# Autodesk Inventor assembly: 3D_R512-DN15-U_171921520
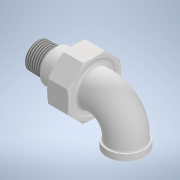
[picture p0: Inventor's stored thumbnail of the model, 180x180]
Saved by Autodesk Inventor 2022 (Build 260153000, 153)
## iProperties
Created: 2021-07
Part Number: 3D_R512-DN15-U_171921520
Document SubType Name: Assembly
Designer: cad
Author: cad
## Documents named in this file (4)
- C:\Users\cad\Desktop\Winkelverschraubung\R-512-U\3D_R512-DN15-U_171921520.iam
- C:\Users\cad\Desktop\Winkelverschraubung\Einzelteile\Mutter\Mutter-DN15.ipt
- C:\Users\cad\Desktop\Winkelverschraubung\Einzelteile\Einschraubteil-R512\Einschraubteil-R512-DN15.ipt
- C:\Users\cad\Desktop\Winkelverschraubung\Einzelteile\Einlegeteil-R512-U\Einlegeteil-R512-U-DN15.ipt
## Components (3 placed, 3 different names)
1. Mutter-DN15:1 — Passend:1, Passend:2, Passend:3, Passend:5
2. Einschraubteil-R512-DN15:1 — Passend:4, Passend:5
3. Einlegeteil-R512-U-DN15:1 — Passend:1, Passend:2, Passend:3, Passend:4
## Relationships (5: Mate 5)
- Passend:1 [Mate]: Mutter-DN15:1 ↔ Einlegeteil-R512-U-DN15:1
- Passend:2 [Mate]: Mutter-DN15:1 ↔ Einlegeteil-R512-U-DN15:1
- Passend:3 [Mate]: Mutter-DN15:1 ↔ Einlegeteil-R512-U-DN15:1
- Passend:4 [Mate]: Einschraubteil-R512-DN15:1 ↔ Einlegeteil-R512-U-DN15:1
- Passend:5 [Mate]: Mutter-DN15:1 ↔ Einschraubteil-R512-DN15:1
